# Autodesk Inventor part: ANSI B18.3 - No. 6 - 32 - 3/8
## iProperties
Author: Elise Moss
Created: 2002-03
Part Number: ANSI B18.3 - No. 6 - 32 - 3/8
Catalog Web Link: file:///C:/Program%20Files/Autodesk/Inventor%205/Content/Ansi/index.htm?doNavigateId=A49C31AC-226A-4717-BB72-3804D842815C|8113466AD7F811D4BA8200C04F798F98|true
Description: Hexagon Socket Head Cap Screw
Document SubType Name: Standard Catalog Part
Standard: ANSI B18.3 - No. 6 - 32 - 3/8
Designer: Elise Moss
CLASSIFICATION: 31161501 un/spsc
MANUFACTURER: ANSI Standard System
Control State: 0
Master: False
Checked Out: False
PropertySet Name: Design Tracking Control
Shininess: 64.0
Angle Display Precision: 2
Document Length Units: 11269
Document Angle Units: 11283
Document Time Units: 11279
Document Mass Units: 11290
Document Length Units Precision: 3
Document Angle Units Precision: 2
Compacted: True
PropertySet Name: _Private Model Information
Density: 0.0
Volumn: 0.0
Area: 0.0
PropertySet Name: Model Information
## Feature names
1. Base1
